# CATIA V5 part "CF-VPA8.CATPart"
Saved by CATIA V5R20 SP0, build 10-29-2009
Part number: CF-VPA8
Bounding box of the stored display mesh (mm): x 0 to 25.5, y -4 to 4, z -4 to 4
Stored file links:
  C:\Users\Utente\Desktop\IO LAVORO\3D X SITO CF\X SITO\PLASTICA\CF-VPA\CF-VPA8.CATPart
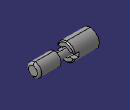
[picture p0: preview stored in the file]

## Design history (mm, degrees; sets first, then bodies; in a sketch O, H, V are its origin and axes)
Set1
  DatumSurface1 to DatumSurface30 "CF-VPA8"
Body1 (main body)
